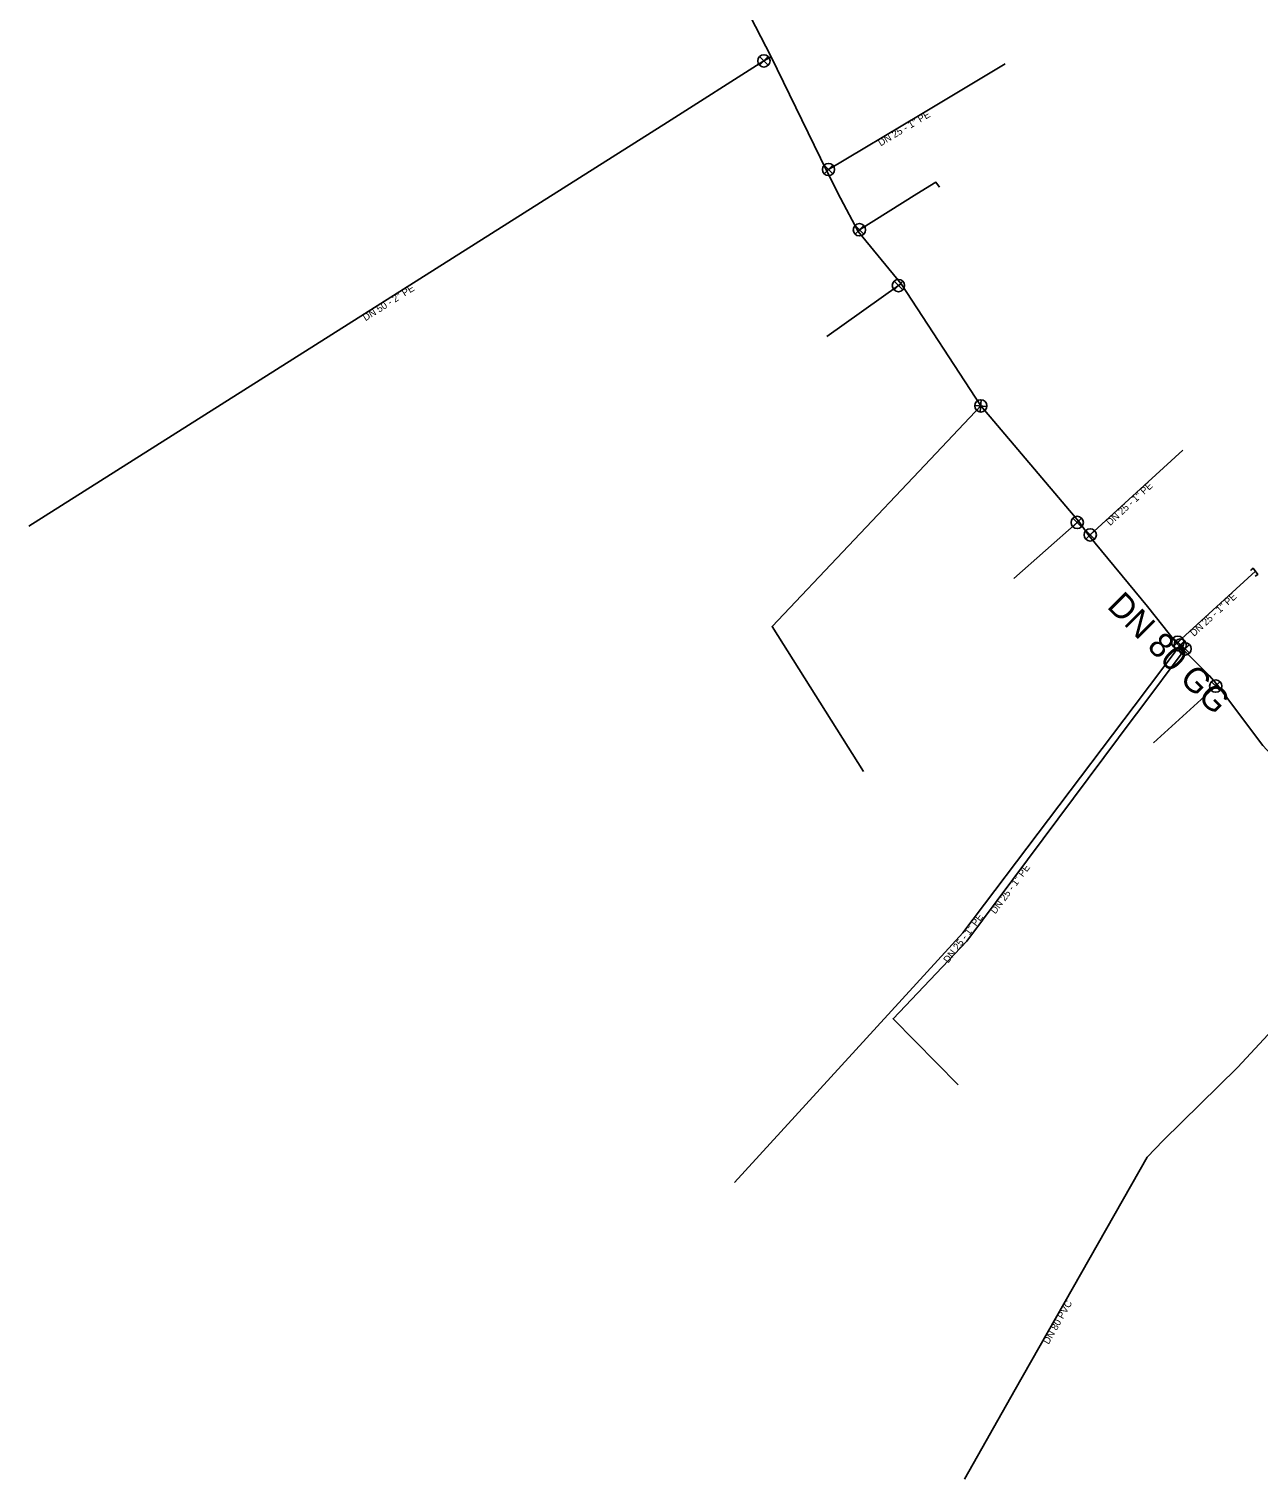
# Model space of a CAD drawing. Extents: x -484784 to -484458, y -1128042 to -1127614.
# Drawn here: x -484588.4 to -484508.5, y -1128041.6 to -1127947.3 of the extents above; entities that cross this region are included whole.
import ezdxf

# ---------------------------------------------------------------- set-up
doc = ezdxf.new("R2010")
doc.units = 0
for name, color, linetype in [('_pripojka_prevzato_z_dokumentace_', 7, 'Continuous'), ('_pripojka_priblizne_', 7, 'Continuous'), ('_voda_smvak_prevzato_z_dokumentace_', 7, 'Continuous'), ('Default', 7, 'Continuous'), ('MoLevel 32', 7, 'Continuous'), ('MoLevel 43', 7, 'Continuous'), ('MoLevel 46', 7, 'Continuous'), ('MoLevel 53', 7, 'Continuous'), ('MoLevel 55', 7, 'Continuous')]:
    doc.layers.add(name, color=color, linetype=linetype)

# ---------------------------------------------------------------- blocks, each defined once
blk = doc.blocks.new('_uzaver_pripojka_')
at = {"layer": 'Default'}
for p, q in [((-0.000035, -0.000035), (0.000035, 0.000035)), ((0.000035, -0.000035), (-0.000035, 0.000035))]:
    blk.add_line(p, q, dxfattribs=at)
for radius in [0.00005, 0.0000025]:
    blk.add_circle((0, 0), radius, dxfattribs=at)
blk = doc.blocks.new('_zaslepeni_')
at = {"layer": 'Default'}
blk.add_lwpolyline([(-0.00004, -0.00005), (0, -0.00005), (0, 0.00005), (-0.00004, 0.00005), (-0.00004, 0.00005)], dxfattribs=at)

msp = doc.modelspace()

# ---------------------------------------------------------------- linework, layer by layer
at = {"layer": '_pripojka_prevzato_z_dokumentace_'}
msp.add_line((-484530.443, -1127952.89), (-484524.912, -1127949.584), dxfattribs=at)
for points in [[(-484536.532, -1127956.516), (-484536.4, -1127956.45), (-484530.443, -1127952.89)], [(-484530.644, -1127958.041), (-484529.411, -1127957.275), (-484529.184, -1127957.589)], [(-484534.478, -1127960.474), (-484534.39, -1127960.37), (-484530.644, -1127958.041)], [(-484531.676, -1127963.881), (-484531.85, -1127964), (-484536.515, -1127967.315)], [(-484519.464, -1127980.256), (-484519.37, -1127980.22), (-484513.343, -1127974.703)], [(-484520.118, -1127979.356), (-484520.22, -1127979.41), (-484524.339, -1127983.058)], [(-484513.731, -1127987.283), (-484513.68, -1127987.21), (-484508.623, -1127982.587)], [(-484511.163, -1127989.903), (-484511.21, -1127990.06), (-484515.248, -1127993.751)], [(-484506.104, -1128010.894), (-484509.795, -1128014.863), (-484514.633, -1128019.619), (-484515.667, -1128020.706), (-484524.251, -1128035.815), (-484527.56, -1128041.639)]]:
    msp.add_lwpolyline(points, dxfattribs=at)
at = {"layer": '_pripojka_priblizne_'}
for p, q in [((-484546.885, -1127953.367), (-484588.415, -1127979.645)), ((-484526.49, -1127971.83), (-484530.143, -1127975.688)), ((-484516.218, -1127991.677), (-484516.504, -1127992.06))]:
    msp.add_line(p, q, dxfattribs=at)
for points in [[(-484540.129, -1127949.131), (-484540.6, -1127949.39), (-484546.885, -1127953.367)], [(-484530.143, -1127975.688), (-484540.07, -1127986.173), (-484534.118, -1127995.618)], [(-484513.597, -1127987.411), (-484513.51, -1127987.39), (-484516.522, -1127991.373)], [(-484513.325, -1127987.673), (-484513.2, -1127987.64), (-484516.218, -1127991.677)], [(-484516.522, -1127991.373), (-484527.67, -1128006.119), (-484542.52, -1128022.352)], [(-484516.504, -1127992.06), (-484527.407, -1128006.644), (-484532.2, -1128011.699), (-484527.971, -1128015.987)]]:
    msp.add_lwpolyline(points, dxfattribs=at)
at = {"layer": '_voda_smvak_prevzato_z_dokumentace_'}
for points in [[(-484552.394, -1127924.476), (-484546.544, -1127936.43), (-484542.52, -1127944.486), (-484540.129, -1127949.131), (-484536.532, -1127956.516), (-484535.627, -1127958.307), (-484534.478, -1127960.474), (-484531.676, -1127963.881), (-484526.49, -1127971.83)], [(-484526.49, -1127971.83), (-484520.118, -1127979.356), (-484519.464, -1127980.256), (-484515.636, -1127984.875), (-484513.731, -1127987.283), (-484513.597, -1127987.411), (-484513.325, -1127987.673), (-484511.629, -1127989.368), (-484511.163, -1127989.903), (-484508.14, -1127993.922), (-484499.415, -1128003.417), (-484498.654, -1128004.24)]]:
    msp.add_lwpolyline(points, dxfattribs=at)

# ---------------------------------------------------------------- block references
at = {"layer": 'MoLevel 43', "xscale": 5000, "yscale": 5000, "rotation": 36.97089948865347}
msp.add_blockref('_zaslepeni_', (-484508.623, -1127982.587), dxfattribs=at)
at = {"layer": 'MoLevel 53', "xscale": 7999.999999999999, "yscale": 7999.999999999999}
for p in [(-484540.6, -1127949.39), (-484536.4, -1127956.45), (-484534.39, -1127960.37), (-484531.85, -1127964), (-484520.22, -1127979.41), (-484519.37, -1127980.22), (-484513.68, -1127987.21), (-484513.51, -1127987.39), (-484513.2, -1127987.64), (-484511.21, -1127990.06)]:
    msp.add_blockref('_uzaver_pripojka_', p, dxfattribs=at)
at = {"layer": 'MoLevel 53', "xscale": 7999.999999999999, "yscale": 7999.999999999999, "rotation": -49.740970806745}
msp.add_blockref('_uzaver_pripojka_', (-484526.49, -1127971.83), dxfattribs=at)

# ---------------------------------------------------------------- texts
at = {"layer": 'MoLevel 32'}
for s, rotation, p in [("DN 50 - 2'' PE", 32.32364, (-484566.518, -1127966.328)), ("DN 25 - 1'' PE", 53.21897, (-484525.547, -1128004.916)), ("DN 25 - 1'' PE", 52.90902, (-484528.605, -1128008.11))]:
    msp.add_text(s, height=0.455, rotation=rotation, dxfattribs=at).set_placement(p)
at = {"layer": 'MoLevel 46'}
msp.add_text('DN 80 GG', height=1.6049, rotation=315.0169, dxfattribs=at).set_placement((-484518.345, -1127984.925))
at = {"layer": 'MoLevel 55'}
for s, rotation, p in [("DN 25 - 1'' PE", 30.86537, (-484533.006, -1127954.952)), ("DN 25 - 1'' PE", 42.47039, (-484518.077, -1127979.653)), ("DN 25 - 1'' PE", 42.43472, (-484512.621, -1127986.859)), ('DN 80 PVC', 60.39744, (-484522.08, -1128032.915))]:
    msp.add_text(s, height=0.455, rotation=rotation, dxfattribs=at).set_placement(p)

doc.saveas('drawing.dxf')
